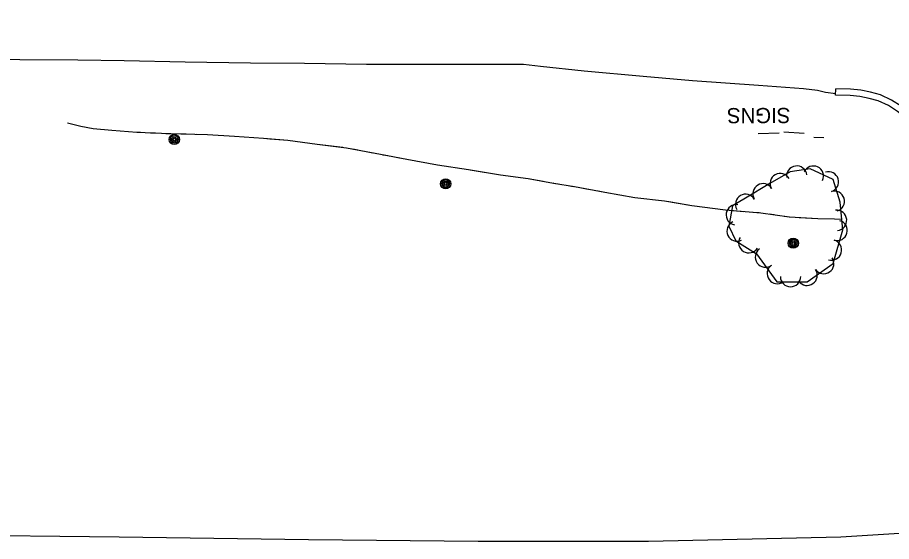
# Model space of a CAD drawing. Extents: x 353423 to 364002, y 127000 to 201942.
# Drawn here: x 357759 to 358103.2, y 132072.1 to 132278.6 of the extents above; entities that cross this region are included whole.
import ezdxf

# ---------------------------------------------------------------- set-up
doc = ezdxf.new("R2010")
doc.units = 0
for name, color, linetype in [('E_DTM_SlopeTop', 7, 'Continuous'), ('E_FEN_Generic', 7, 'Continuous'), ('E_LAND_BrushLine', 7, 'Continuous'), ('E_RDWY_Gravel', 7, 'Continuous'), ('E_STRUCT_WingWall', 7, 'Continuous')]:
    doc.layers.add(name, color=color, linetype=linetype)

msp = doc.modelspace()

# ---------------------------------------------------------------- linework, layer by layer
at = {"layer": 'E_DTM_SlopeTop'}
for points in [[(357740.17, 132262.27), (357759.91, 132262.09), (357782.79, 132261.89), (357801.04, 132261.59), (357825.07, 132261.12), (357850.72, 132260.69), (357872.07, 132260.58), (357896.4, 132260.24), (357923.2, 132260.27), (357946.56, 132260.15), (357958.3, 132260.24), (357964.97, 132259.39), (357982.23, 132257.52), (358005.4, 132255.49), (358024.87, 132253.82), (358050.81, 132251.94), (358068.62, 132250.62), (358074.06, 132249.95), (358077.16, 132249.12), (358081.23, 132248.66)], [(358122.86, 132210.92), (358122.14, 132215.87), (358121.12, 132220.32), (358119.68, 132224.48), (358118.16, 132227.93), (358116.42, 132231.07), (358114.83, 132233.39), (358112.02, 132236.29), (358109.14, 132238.91), (358105.63, 132241.58), (358102.06, 132243.86), (358097.95, 132245.72), (358094.38, 132246.74), (358090.75, 132247.48), (358086.9, 132247.8), (358081.22, 132247.96), (358081.29, 132250.46)], [(358122.86, 132210.92), (358125.34, 132211.28), (358124.6, 132216.33), (358123.53, 132221.01), (358122.01, 132225.4), (358120.4, 132229.04), (358118.55, 132232.39), (358116.77, 132234.98), (358113.76, 132238.08), (358110.74, 132240.83), (358107.06, 132243.63), (358103.25, 132246.06), (358098.82, 132248.07), (358094.97, 132249.17), (358091.1, 132249.96), (358087.04, 132250.29), (358081.29, 132250.46)]]:
    msp.add_lwpolyline(points, dxfattribs=at)
at = {"layer": 'E_FEN_Generic'}
msp.add_lwpolyline([(358084.04, 132194.88), (358083.01, 132205.77), (358080.26, 132214.81), (358071.19, 132218.96), (358063.35, 132217.82), (358055.24, 132213.2), (358045.75, 132207.39), (358040.54, 132204.37), (358039.21, 132196.38), (358041.89, 132190.58), (358050.11, 132185.41), (358058.03, 132174.38), (358069.94, 132174.39), (358080.2, 132181.63)], close=True, dxfattribs=at)
for centre, start, end in [((358065.92, 132216.08), 8.2619, 188.2466), ((358072.47, 132216.07), 335.4484, 155.4331), ((358059.43, 132213.18), 29.6779, 209.6626), ((358078.37, 132213.83), 286.9018, 106.8865), ((358052.6, 132209.13), 31.4753, 211.46), ((358080.7, 132206.17), 286.9018, 106.8865), ((358045.72, 132204.96), 30.1569, 210.1416), ((358042.08, 132200.84), 80.5429, 260.5275), ((358081.58, 132198.66), 275.4086, 95.3933), ((358042.42, 132194.42), 114.8105, 294.7952), ((358081.8, 132194.67), 253.8582, 73.8429), ((358047.01, 132189.83), 147.8702, 327.8549), ((358079.57, 132186.99), 253.8582, 73.8429), ((358053.57, 132184.18), 125.6895, 305.6742), ((358076.52, 132181.59), 215.2373, 35.2219), ((358058.24, 132177.68), 125.6895, 305.6742), ((358069.98, 132176.98), 215.2373, 35.2219), ((358063.47, 132176.48), 180.0186, 0.0033)]:
    msp.add_arc(centre, 4, start, end, dxfattribs=at)
at = {"layer": 'E_LAND_BrushLine'}
for points in [[(358060.77, 132233.54), (358068.85, 132232.97)], [(358058.98, 132233), (358050.77, 132232.8)], [(358072.58, 132231.5), (358076.62, 132231.3)]]:
    msp.add_lwpolyline(points, dxfattribs=at)
for centre, radius in [((357820.78, 132230.54), 2.02), ((357820.77, 132230.56), 1.52), ((357820.78, 132230.52), 1.01), ((357820.78, 132230.53), 0.502), ((357927.64, 132213.04), 2.02), ((357927.64, 132213.05), 1.52), ((357927.65, 132213.01), 1.01), ((357927.65, 132213.02), 0.502), ((358064.54, 132189.67), 2.02), ((358064.54, 132189.68), 1.52), ((358064.54, 132189.64), 1.01), ((358064.55, 132189.65), 0.502)]:
    msp.add_circle(centre, radius, dxfattribs=at)
at = {"layer": 'E_RDWY_Gravel'}
msp.add_lwpolyline([(358414.98, 132117.79), (358379.2, 132108.99), (358327.51, 132097.87), (358262.06, 132088.14), (358198.37, 132081.55), (358144.33, 132077.59), (358083.26, 132073.84), (358007.46, 132072.15), (357940.41, 132072.08), (357873.59, 132072.81), (357799.01, 132073.84), (357728.92, 132074.58), (357662.2, 132075.55), (357539.69, 132077.09), (357418.95, 132079.48), (357361.42, 132080.9), (357283.11, 132082.67), (357216.19, 132081.97), (357123.22, 132082.45), (356998.35, 132083.14), (356873.58, 132084.18), (356873.17, 132284.46)], dxfattribs=at)
at = {"layer": 'E_STRUCT_WingWall'}
for points in [[(357778.71, 132237.02), (357783.93, 132235.75), (357788.82, 132234.86), (357796.21, 132234.13), (357805.99, 132233.47), (357819, 132232.83), (357833.81, 132232.51), (357844.48, 132231.8), (357855.92, 132231), (357865.44, 132230.29), (357877, 132228.64), (357888.65, 132227.28), (357902.03, 132224.68), (357912.39, 132222.73), (357924.46, 132220.57), (357936.61, 132218.74), (357949.28, 132216.65), (357960.16, 132215.17), (357970.14, 132213.36), (357978.38, 132211.94), (357990.28, 132209.77), (358002.17, 132207.65), (358013.86, 132206.29), (358024.57, 132204.55), (358037.79, 132202.8), (358051.73, 132201.64), (358062.99, 132200.08), (358074.26, 132199.36), (358080.77, 132199.27), (358083.75, 132199.17)], [(357778.71, 132237.02), (357783.93, 132235.75), (357788.82, 132234.86), (357796.21, 132234.13), (357805.99, 132233.47), (357807.41, 132233.4)], [(357811.41, 132233.2), (357813.41, 132233.1)], [(357817.4, 132232.9), (357819, 132232.83), (357819.4, 132232.82)], [(357823.4, 132232.73), (357825.4, 132232.69)], [(357829.4, 132232.61), (357833.81, 132232.51), (357844.48, 132231.8), (357855.92, 132231), (357858.34, 132230.82)], [(357858.34, 132230.82), (357865.44, 132230.29), (357877, 132228.64), (357887.13, 132227.46)], [(357891.08, 132226.81), (357893.04, 132226.42)], [(357896.97, 132225.66), (357898.93, 132225.28)], [(357902.86, 132224.52), (357904.82, 132224.15)], [(357908.75, 132223.42), (357912.39, 132222.73), (357924.46, 132220.57), (357936.61, 132218.74), (357937.35, 132218.61)], [(357937.35, 132218.61), (357949.28, 132216.65), (357960.16, 132215.17), (357965.99, 132214.11)], [(357969.93, 132213.39), (357970.14, 132213.36), (357971.9, 132213.05)], [(357975.84, 132212.37), (357977.81, 132212.04)], [(357981.75, 132211.32), (357983.72, 132210.96)], [(357987.65, 132210.25), (357990.28, 132209.77), (358002.17, 132207.65), (358013.86, 132206.29), (358016.31, 132205.89)], [(358016.31, 132205.89), (358024.57, 132204.55), (358037.79, 132202.8), (358045.06, 132202.2)], [(358049.05, 132201.87), (358051.04, 132201.7)], [(358055.01, 132201.19), (358056.99, 132200.91)], [(358060.95, 132200.36), (358062.93, 132200.08)], [(358066.92, 132199.83), (358074.26, 132199.36), (358080.77, 132199.27), (358083.75, 132199.17)]]:
    msp.add_lwpolyline(points, dxfattribs=at)

# ---------------------------------------------------------------- texts
at = {"layer": 'E_LAND_BrushLine'}
msp.add_text('SIGNS', height=6, rotation=180.1741, dxfattribs=at).set_placement((358063.39, 132242.99))

doc.saveas('drawing.dxf')
